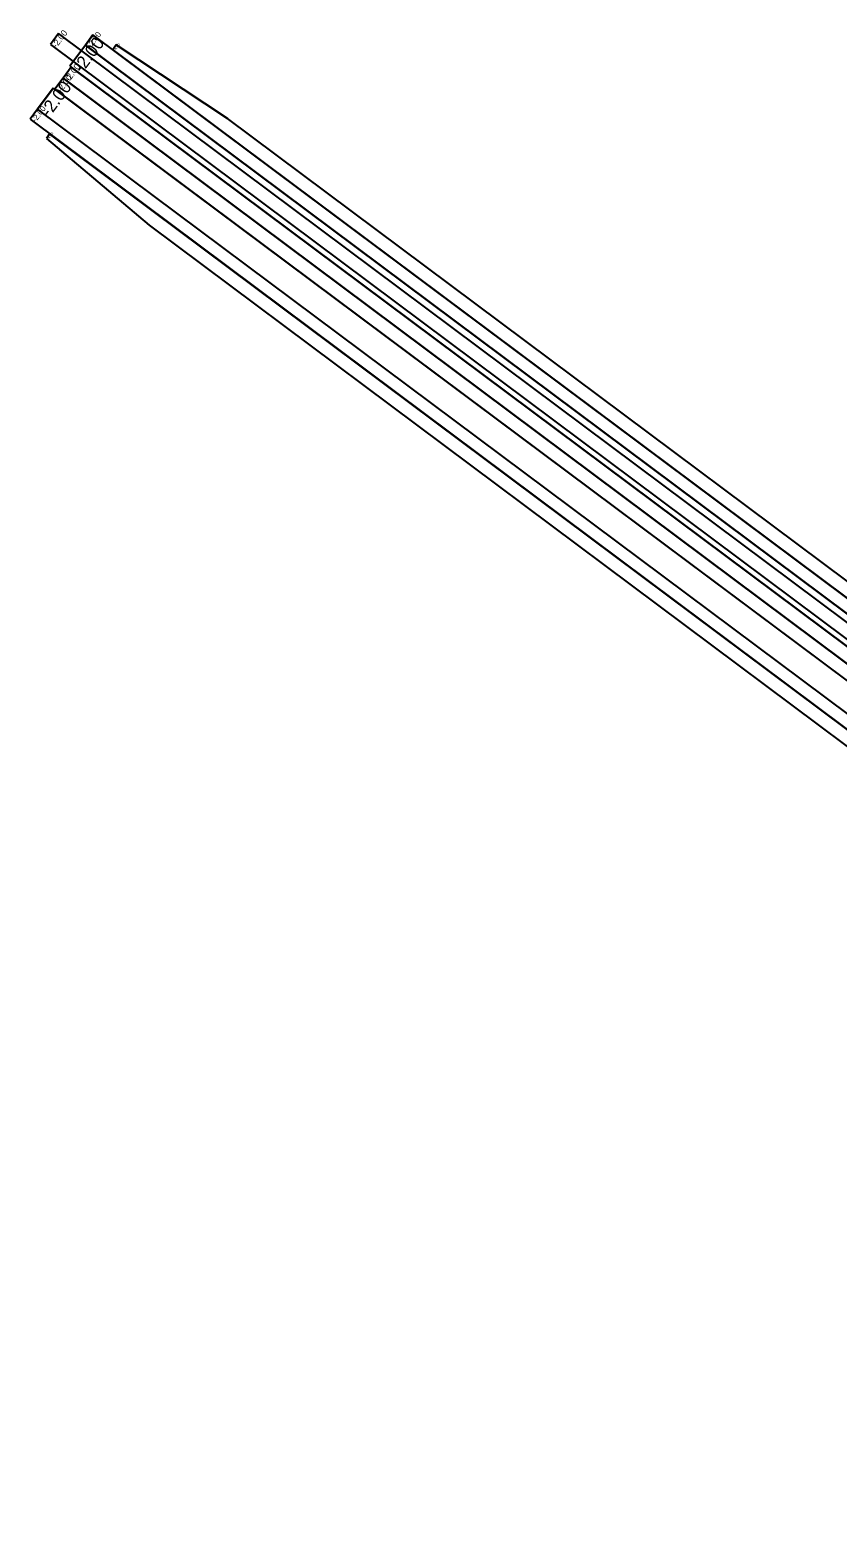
# Model space of a CAD drawing. Extents: x 2342222 to 2351711, y 366548 to 372860.
# Drawn here: x 2342222 to 2342929, y 371541 to 372860 of the extents above; entities that cross this region are included whole.
import ezdxf

# ---------------------------------------------------------------- set-up
doc = ezdxf.new("R2010")
doc.units = 0
for name, color, linetype in [('RD_PD_PaveShd', 7, 'Continuous'), ('RD_PD_SuperShp_BL_EB_526', 7, 'Continuous'), ('RD_PD_SuperShp_BL_WB_526', 7, 'Continuous'), ('RD_PD_SuperShp_WB_526', 7, 'Continuous')]:
    doc.layers.add(name, color=color, linetype=linetype)

msp = doc.modelspace()

# ---------------------------------------------------------------- linework, layer by layer
at = {"layer": 'RD_PD_PaveShd'}
for p, q in [((2342297.3, 372846.9), (2342394.8, 372782.6)), ((2342250.8, 372817.8), (2343171.6, 372130.5)), ((2343086.7, 372266.2), (2342394.8, 372782.6))]:
    msp.add_line(p, q, dxfattribs=at)
at = {"layer": 'RD_PD_SuperShp_BL_EB_526'}
for p, q in [((2342228.5, 372790.7), (2342242.2, 372809.1)), ((2342242.2, 372809.1), (2343465, 371896.5)), ((2342250.8, 372817.8), (2342243.6, 372808.1)), ((2342243.6, 372808.1), (2343212.6, 372084.9)), ((2343219.8, 372094.5), (2342250.8, 372817.8)), ((2342228.5, 372790.7), (2342221.9, 372781.9)), ((2342221.9, 372781.9), (2343444.7, 371869.3)), ((2343451.3, 371878.1), (2342228.5, 372790.7)), ((2343451.3, 371878.1), (2342228.5, 372790.7)), ((2342239, 372769.1), (2342236.1, 372765.1)), ((2343167.7, 372076), (2342239, 372769.1)), ((2342236.1, 372765.1), (2342326.1, 372689.1)), ((2342326.1, 372689.1), (2343058.4, 372142.6))]:
    msp.add_line(p, q, dxfattribs=at)
at = {"layer": 'RD_PD_SuperShp_BL_WB_526'}
for p, q in [((2342270.3, 372846.8), (2342256.6, 372828.4)), ((2342270.3, 372846.8), (2342276.9, 372855.6)), ((2342276.9, 372855.6), (2342270.3, 372846.8)), ((2343458.6, 371959.9), (2342270.3, 372846.8)), ((2342270.3, 372846.8), (2343458.6, 371959.9)), ((2343465.2, 371968.7), (2342276.9, 372855.6)), ((2342297.3, 372846.9), (2342294.2, 372842.7)), ((2342394.8, 372782.6), (2342297.3, 372846.9)), ((2342294.2, 372842.7), (2343174.7, 372185.5)), ((2342257.9, 372827.4), (2342250.8, 372817.8)), ((2342256.6, 372828.4), (2343444.9, 371941.5)), ((2343178.8, 372140.1), (2342257.9, 372827.4)), ((2342242.2, 372809.1), (2342228.5, 372790.7)), ((2342250.8, 372817.8), (2343171.6, 372130.5)), ((2343084.8, 372267.7), (2342394.8, 372782.6))]:
    msp.add_line(p, q, dxfattribs=at)
at = {"layer": 'RD_PD_SuperShp_WB_526'}
for p, q in [((2342246.7, 372856.9), (2342239.6, 372847.3)), ((2342239.6, 372847.3), (2345207.1, 370632.5)), ((2345214.3, 370642.1), (2342246.7, 372856.9))]:
    msp.add_line(p, q, dxfattribs=at)

# ---------------------------------------------------------------- texts
at = {"layer": 'RD_PD_SuperShp_BL_EB_526'}
for s, height, rotation, p in [('-2.00', 5.52, 53.2637, (2342249, 372804.7)), ('-2.00', 11.04, 53.2637, (2342238.7, 372783.1)), ('-2.00', 5.06, 53.2637, (2342226.8, 372778.8)), ('-4.00', 2.28, 53.2189, (2342238.2, 372763.7))]:
    msp.add_text(s, height=height, rotation=rotation, dxfattribs=at).set_placement(p)
at = {"layer": 'RD_PD_SuperShp_BL_WB_526'}
for s, height, p in [('-2.00', 11.04, (2342267.4, 372821.5)), ('-2.00', 5.06, (2342275.3, 372843.7)), ('-4.00', 2.38, (2342296.5, 372841.3)), ('-2.00', 5.52, (2342256.1, 372814.3))]:
    msp.add_text(s, height=height, rotation=53.2637, dxfattribs=at).set_placement(p)
at = {"layer": 'RD_PD_SuperShp_WB_526'}
msp.add_text('-2.00', height=5.52, rotation=53.2637, dxfattribs=at).set_placement((2342244.9, 372843.9))
msp.add_text('-2.00', height=5.52, rotation=53.2637, dxfattribs=at).set_placement((2342244.9, 372843.9))

doc.saveas('drawing.dxf')
